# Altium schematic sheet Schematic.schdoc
size 127 x 101 mm
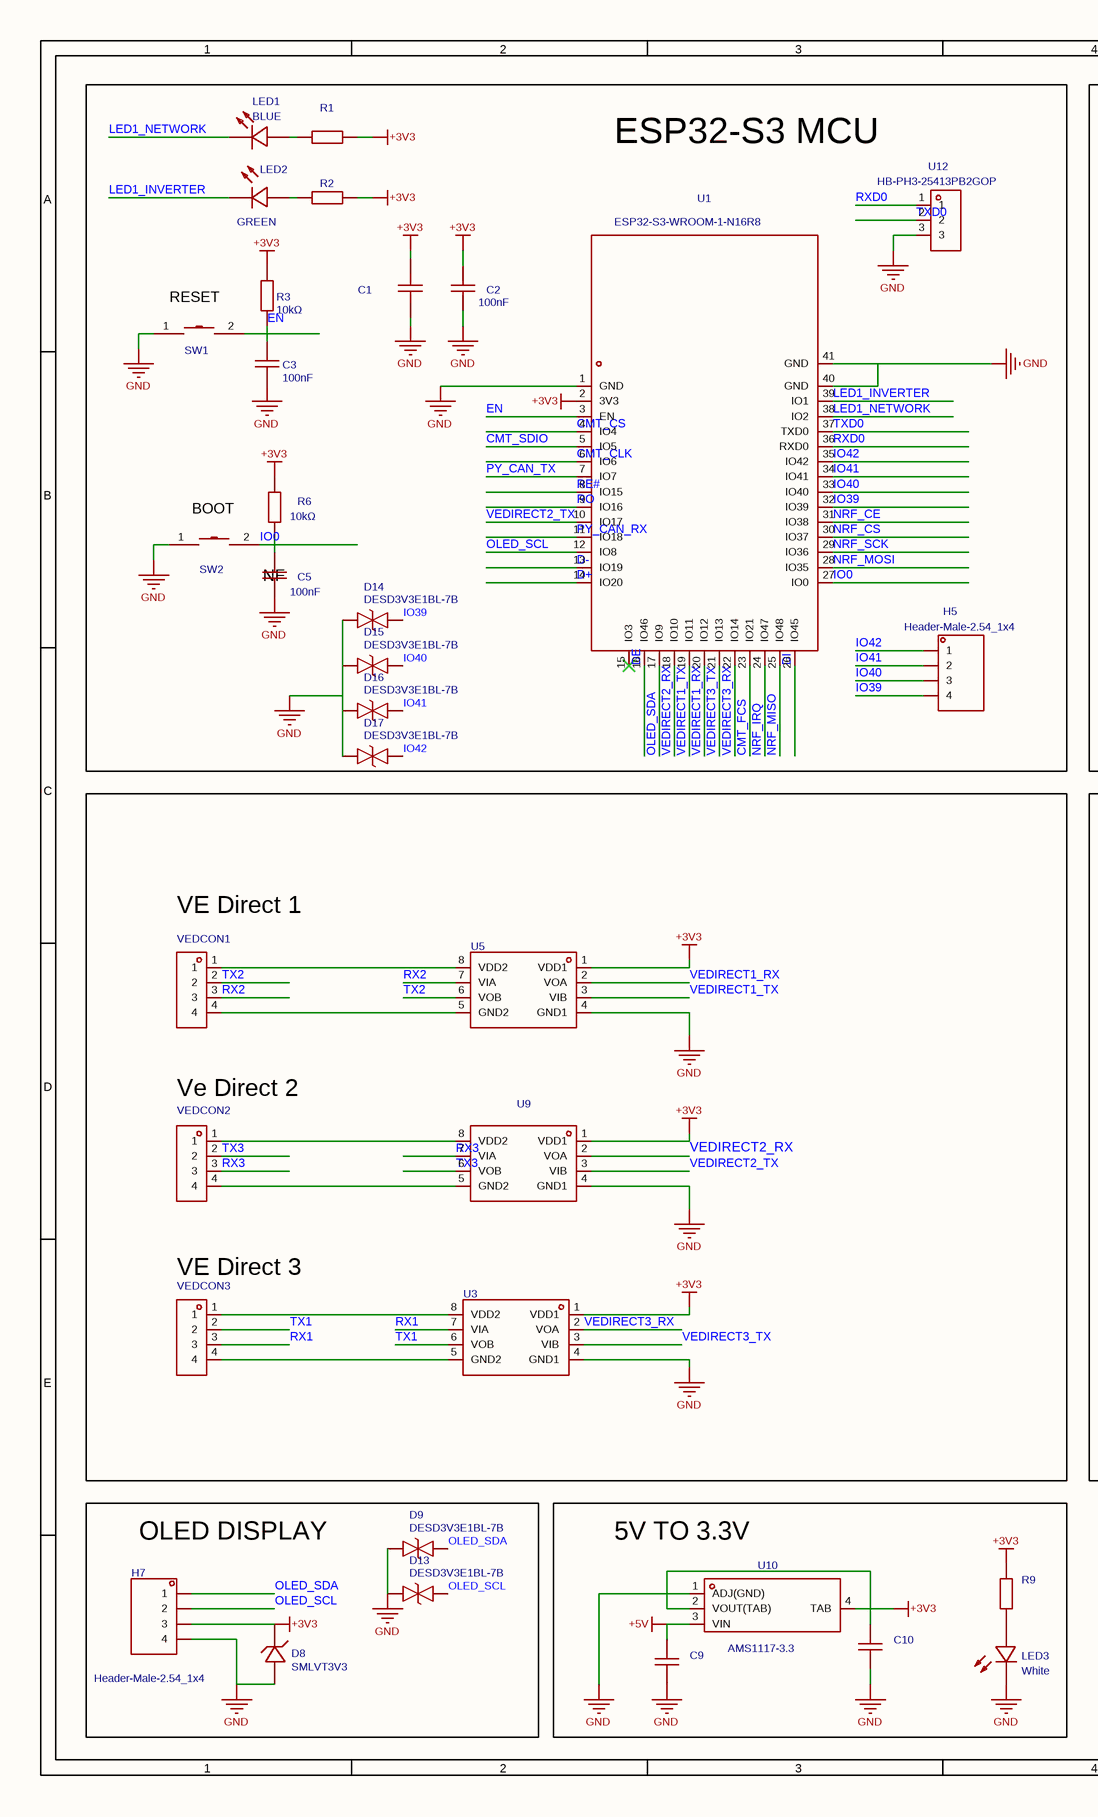
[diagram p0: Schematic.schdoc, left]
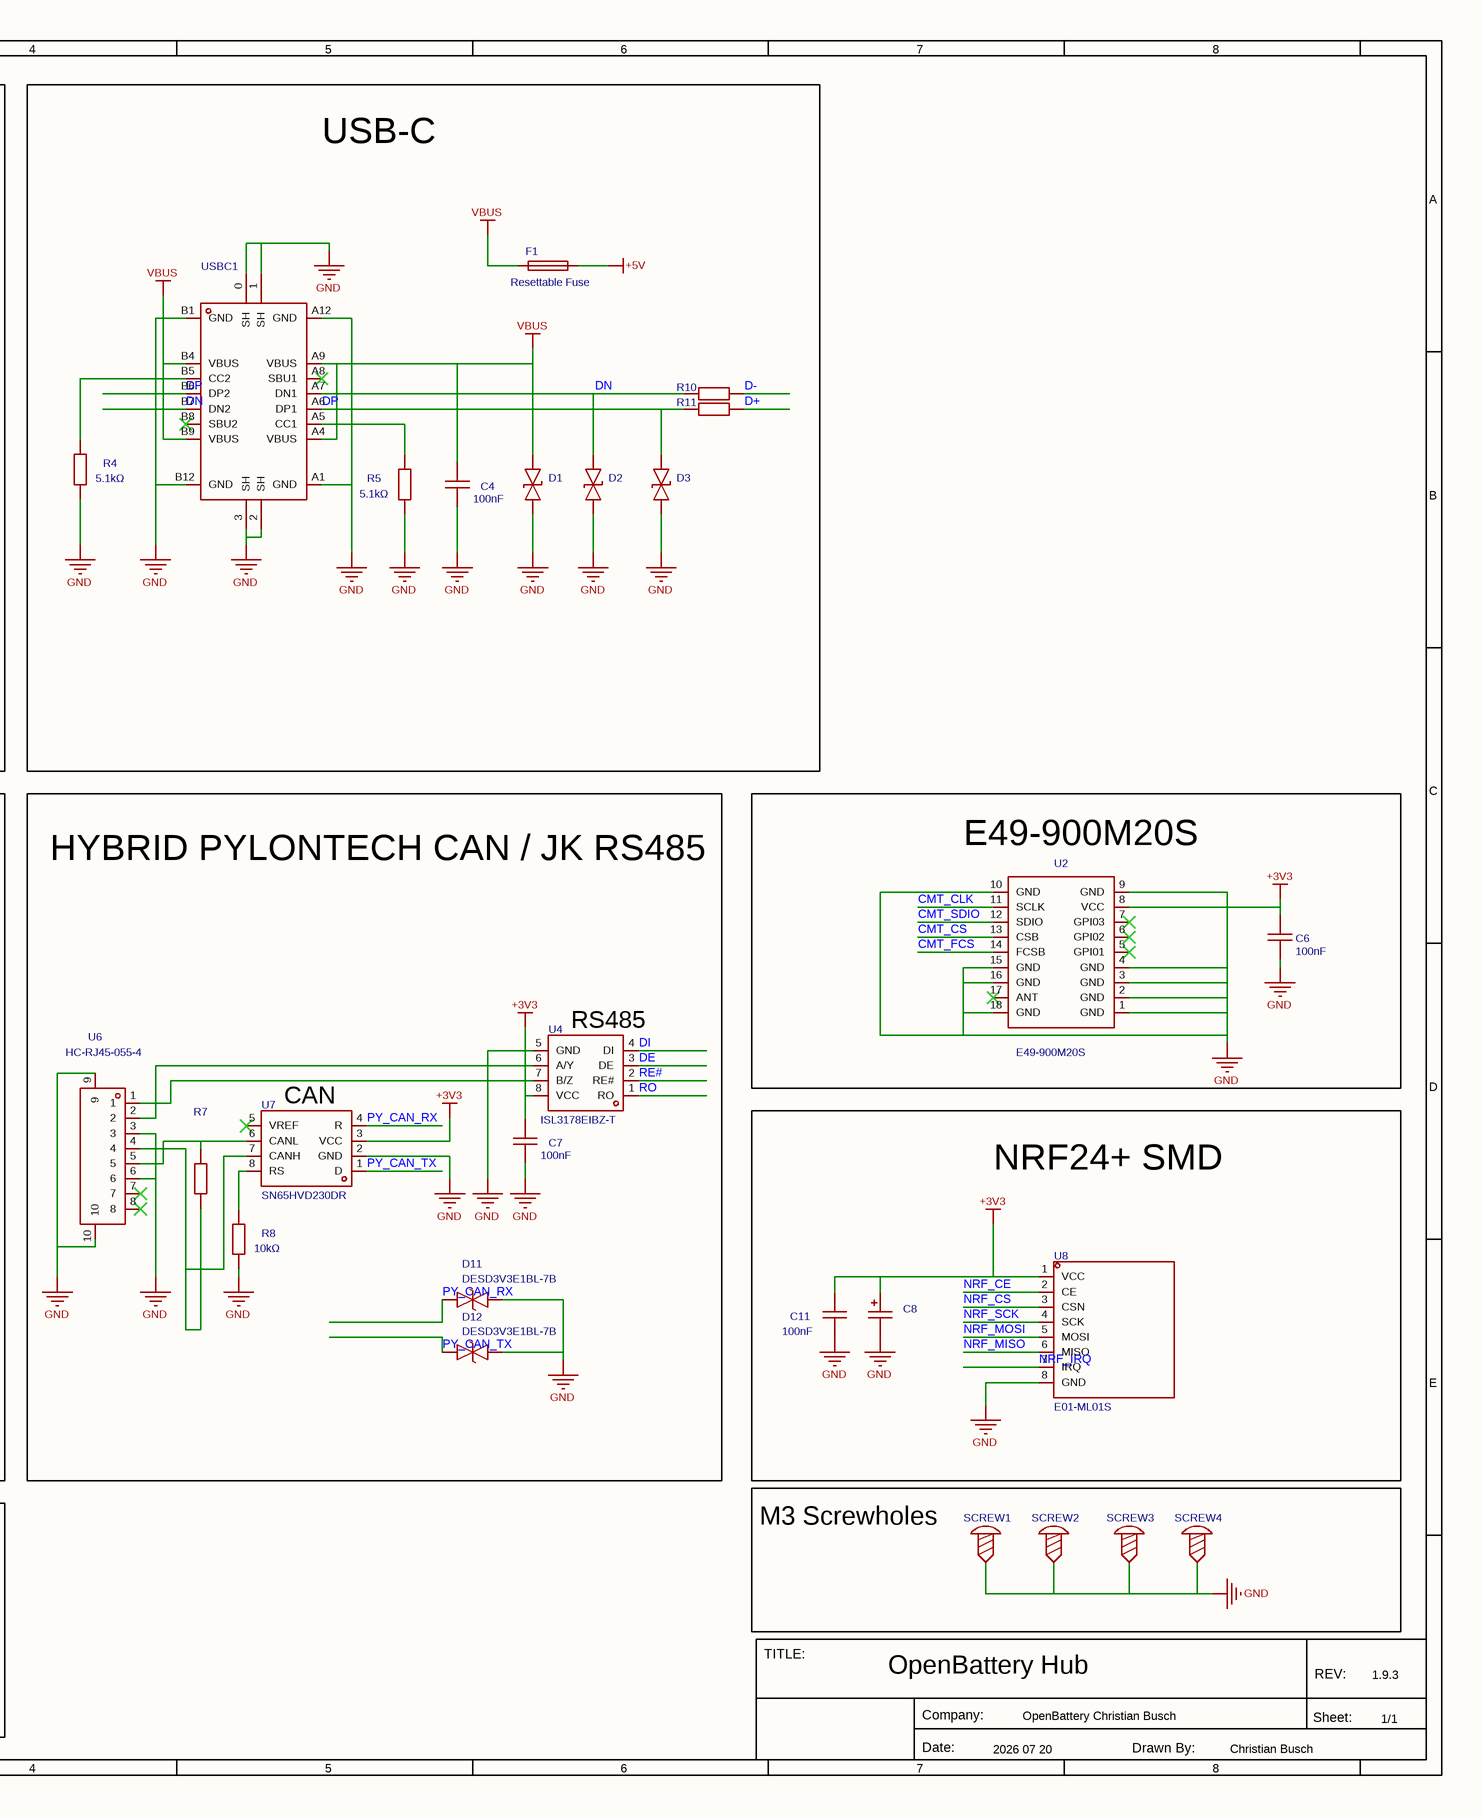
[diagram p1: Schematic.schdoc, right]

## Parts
C1  22uF  [C0402_4]  (value not drawn)
C2  100nF  [C0402_4]
C3  100nF  [C0402_4]
C4  100nF  [C0402_4]
C5  100nF  [C0402_4]
C6  100nF  [C0402_4]
C7  100nF  [C0402_4]
C8  100uF  [CASE-B_3531]  (value not drawn)
C9  10uF  [C0402_4]  (value not drawn)
C10  10uF  [C0402_4]  (value not drawn)
C11  100nF  [C0402_4]
D1  LESD5D5.0CT1G  [SOD-523_L1.2-W0.8-LS1.6-BI_4]  (value not drawn)
D2  LESD5D5.0CT1G  [SOD-523_L1.2-W0.8-LS1.6-BI_4]  (value not drawn)
D3  LESD5D5.0CT1G  [SOD-523_L1.2-W0.8-LS1.6-BI_4]  (value not drawn)
D8  SMLVT3V3  [SMB_L4.6-W3.6-LS5.3-RD_3]
D9  DESD3V3E1BL-7B  [X1-DFN1006-2_L1.0-W0.6-P0.65-BI_2]
D11  DESD3V3E1BL-7B  [X1-DFN1006-2_L1.0-W0.6-P0.65-BI_2]
D12  DESD3V3E1BL-7B  [X1-DFN1006-2_L1.0-W0.6-P0.65-BI_2]
D13  DESD3V3E1BL-7B  [X1-DFN1006-2_L1.0-W0.6-P0.65-BI_2]
D14  DESD3V3E1BL-7B  [X1-DFN1006-2_L1.0-W0.6-P0.65-BI_2]
D15  DESD3V3E1BL-7B  [X1-DFN1006-2_L1.0-W0.6-P0.65-BI_2]
D16  DESD3V3E1BL-7B  [X1-DFN1006-2_L1.0-W0.6-P0.65-BI_2]
D17  DESD3V3E1BL-7B  [X1-DFN1006-2_L1.0-W0.6-P0.65-BI_2]
F1  Resettable Fuse  [F1206_3]
H5  Header-Male-2.54_1x4  [HDR-TH_4P-P2.54-V-M_3]
H7  Header-Male-2.54_1x4  [HDR-TH_4P-P2.54-V-M_3]
LED1  BLUE  [LED0402-R-RD_3]
LED2  GREEN  [LED0402-RD_GREEN_3]
LED3  White  [LED0402-RD_WHITE_3]
R1  1.5kΩ  [R0402_3]  (value not drawn)
R2  1.5kΩ  [R0402_3]  (value not drawn)
R3  10kΩ  [R0402_3]
R4  5.1kΩ  [R0402_3]
R5  5.1kΩ  [R0402_3]
R6  10kΩ  [R0402_3]
R7  120Ω  [R0402_3]  (value not drawn)
R8  10kΩ  [R0402_3]
R9  1.5kΩ  [R0402_3]  (value not drawn)
R10  22Ω  [R0402_3]  (value not drawn)
R11  22Ω  [R0402_3]  (value not drawn)
SCREW1  (no value)  [Screw-Hole-M2]
SCREW2  (no value)  [Screw-Hole-M2]
SCREW3  (no value)  [Screw-Hole-M2]
SCREW4  (no value)  [Screw-Hole-M2]
SW1  TS-1101-C-W  [SW-SMD_L6.0-W3.3-LS8.0_3]  (value not drawn)
SW2  TS-1101-C-W  [SW-SMD_L6.0-W3.3-LS8.0_3]  (value not drawn)
U1  ESP32-S3-WROOM-1-N16R8  [WIRELM-SMD_ESP32-S3-WROOM-1_4]
U2  E49-900M20S  [WIRELM-SMD_E49-400M20S_3]
U3  ADUM1201AR-RL7  [SOIC-8_L4.9-W3.9-P1.27-LS6.0-BL_3]  (value not drawn)
U4  ISL3178EIBZ-T  [SOIC-8_L4.9-W3.9-P1.27-LS6.0-BL_3]
U5  ADUM1201AR-RL7  [SOIC-8_L4.9-W3.9-P1.27-LS6.0-BL_3]  (value not drawn)
U6  HC-RJ45-055-4  [RJ45-SMD_HC-RJ45-055-4_5]
U7  SN65HVD230DR  [SOIC-8_L4.9-W3.9-P1.27-LS6.0-BL_3]
U8  E01-ML01S  [WIRELM-SMD_E01-ML01S_3]
U9  ADUM1201AR-RL7  [SOIC-8_L4.9-W3.9-P1.27-LS6.0-BL_3]  (value not drawn)
U10  AMS1117-3.3  [SOT-223-4_L6.5-W3.5-P2.30-LS7.0-BR_3]
U12  HB-PH3-25413PB2GOP  [HDR-TH_3P-P2.54-V-M_3]
USBC1  TYPE-C-31-M-12  [USB-C_SMD-TYPE-C-31-M-12_3]  (value not drawn)
VEDCON1  PH-4AW_C722777  [CONN-TH_PH-4AW_C722777_3]  (value not drawn)
VEDCON2  PH-4AW_C722777  [CONN-TH_PH-4AW_C722777_3]  (value not drawn)
VEDCON3  PH-4AW_C722777  [CONN-TH_PH-4AW_C722777_3]  (value not drawn)

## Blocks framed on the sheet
E49-900M20S: C6 U2
NRF24+ SMD: C8 C11 U8
M3 Screwholes: SCREW1-SCREW4
OLED DISPLAY: D8 D9 D13 H7
5V TO 3.3V: C9 C10 LED3 R9 U10

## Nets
+3V3: C1.2 C2.2 C6.2 C7.2 C8.1 C10.2 C11.1 D8.1(C) H7.3 R1.1 R2.1 R3.2 R6.2 R9.2 U1.2(3V3) U2.8(VCC) U3.1(VDD1) U4.8(VCC) U5.1(VDD1) U7.3(VCC) U8.1(VCC) U9.1(VDD1) U10.2(VOUT(TAB)) U10.4(TAB)
+5V: C9.1 F1.2 U10.3(VIN)
GND: C1.1 C2.1 C3.1 C4.1 C5.1 C6.1 C7.1 C8.2 C9.2 C10.1 C11.2 D1.1 D2.1 D3.1 D8.2(A) D9.1 D11.2 D12.2 D13.1 D14.1 D15.1 D16.1 D17.1 H7.4 LED3.1(C) R4.1 R5.1 R8.1 SCREW1.1 SCREW2.1 SCREW3.1 SCREW4.1 SW1.1 SW2.1 U1.1(GND) U1.40(GND) U1.41(GND) U2.1(GND) U2.2(GND) U2.3(GND) U2.4(GND) U2.9(GND) U2.10(GND) U2.15(GND) U2.16(GND) U2.18(GND) U3.4(GND1) U4.5(GND) U5.4(GND1) U6.3 U6.6 U6.9 U6.10 U7.2(GND) U8.8(GND) U9.4(GND1) U10.1(ADJ(GND)) U12.3 USBC1.0(SH) USBC1.1(SH) USBC1.2(SH) USBC1.3(SH) USBC1.A1(GND) USBC1.A12(GND) USBC1.B1(GND) USBC1.B12(GND)
VBUS: C4.2 D1.2 F1.1 USBC1.A4(VBUS) USBC1.A9(VBUS) USBC1.B4(VBUS) USBC1.B9(VBUS)
CMT_CLK: U1.6(IO6) U2.11(SCLK)
CMT_CS: U1.4(IO4) U2.13(CSB)
CMT_FCS: U1.23(IO21) U2.14(FCSB)
CMT_SDIO: U1.5(IO5) U2.12(SDIO)
D+: R11.2 U1.14(IO20)
D-: R10.2 U1.13(IO19)
DE: U1.16(IO46) U4.3(DE)
DI: U1.26(IO45) U4.4(DI)
DN: D2.2 R10.1 USBC1.A7(DN1) USBC1.B7(DN2)
DP: D3.2 R11.1 USBC1.A6(DP1) USBC1.B6(DP2)
EN: C3.2 R3.1 SW1.2 U1.3(EN)
IO0: C5.2 R6.1 SW2.2 U1.27(IO0)
IO39: D14.2 H5.4 U1.32(IO39)
IO40: D15.2 H5.3 U1.33(IO40)
IO41: D16.2 H5.2 U1.34(IO41)
IO42: D17.2 H5.1 U1.35(IO42)
LED1_INVERTER: LED2.1(C) U1.39(IO1)
LED1_NETWORK: LED1.2(K) U1.38(IO2)
NRF_CE: U1.31(IO38) U8.2(CE)
NRF_CS: U1.30(IO37) U8.3(CSN)
NRF_IRQ: U1.24(IO47) U8.7(IRQ)
NRF_MISO: U1.25(IO48) U8.6(MISO)
NRF_MOSI: U1.28(IO35) U8.5(MOSI)
NRF_SCK: U1.29(IO36) U8.4(SCK)
OLED_SCL: D13.2 H7.2 U1.12(IO8)
OLED_SDA: D9.2 H7.1 U1.17(IO9)
PY_CAN_RX: D11.1 U1.11(IO18) U7.4(R)
PY_CAN_TX: D12.1 U1.7(IO7) U7.1(D)
RE#: U1.8(IO15) U4.2(RE#)
RO: U1.9(IO16) U4.1(RO)
RX1: U3.7(VIA) VEDCON3.3
RX2: U5.7(VIA) VEDCON1.3
RX3: U9.7(VIA) VEDCON2.3
RXD0: U1.36(RXD0) U12.1
TX1: U3.6(VOB) VEDCON3.2
TX2: U5.6(VOB) VEDCON1.2
TX3: U9.6(VOB) VEDCON2.2
TXD0: U1.37(TXD0) U12.2
VEDIRECT1_RX: U1.20(IO12) U5.2(VOA)
VEDIRECT1_TX: U1.19(IO11) U5.3(VIB)
VEDIRECT2_RX: U1.18(IO10) U9.2(VOA)
VEDIRECT2_TX: U1.10(IO17) U9.3(VIB)
VEDIRECT3_RX: U1.22(IO14) U3.2(VOA)
VEDIRECT3_TX: U1.21(IO13) U3.3(VIB)
NetLED1_1: LED1.1(A) R1.2
NetLED2_2: LED2.2(A) R2.2
NetLED3_2: LED3.2(A) R9.1
NetR4_2: R4.2 USBC1.B5(CC2)
NetR5_2: R5.2 USBC1.A5(CC1)
NetR7_1: R7.1 U6.4 U7.7(CANH)
NetR7_2: R7.2 U6.5 U7.6(CANL)
NetR8_2: R8.2 U7.8(RS)
NetU3_5: U3.5(GND2) VEDCON3.4
NetU3_8: U3.8(VDD2) VEDCON3.1
NetU4_6: U4.6(A/Y) U6.2
NetU4_7: U4.7(B/Z) U6.1
NetU5_5: U5.5(GND2) VEDCON1.4
NetU5_8: U5.8(VDD2) VEDCON1.1
NetU9_5: U9.5(GND2) VEDCON2.4
NetU9_8: U9.8(VDD2) VEDCON2.1

Not connected (* = marked no-connect by the designer): U1 15(IO3)*; U2 5(GPI01)* 6(GPI02)* 7(GPI03)* 17(ANT)*; U6 7* 8*; U7 5(VREF)*; USBC1 A8(SBU1)* B8(SBU2)*

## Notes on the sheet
- 1
- 2
- 3
- 4
- 5
- 6
- 7
- 8
- ESP32-S3 MCU
- USB-C
- A
- (near SW1) RESET
- B
- (near SW2) BOOT
- (near C5) NF
- C
- HYBRID PYLONTECH CAN / JK RS485
- (near VEDCON1) VE Direct 1
- D
- (near VEDCON2) Ve Direct 2
- (near U4) RS485
- (near U7) CAN
- (near VEDCON3) VE Direct 3
- E
- TITLE:
- OpenBattery Hub
- REV:
- 1.9.3
- Date:
- Company:
- 2026 07 20
- OpenBattery Christian Busch
- Drawn By:
- Christian Busch
- Sheet:
- 1/1

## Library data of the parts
C1 = 22uF_1: Manufacturer: muRata(村田); Manufacturer Part: GRM155R60J226ME11D; Origin Footprint: C0402; Add into BOM: yes; Tolerance: ±20%; ModelId: 89fda7647e4f421c9745a20fb37cf343
C2-C7 C11 = 100nF_1: Manufacturer Part: CL05B104KO5NNNC; Manufacturer: SAMSUNG(三星); Convert to PCB: yes; Origin Footprint: C0402; ModelId: 89fda7647e4f421c9745a20fb37cf343
C8 = 100uF_1: Manufacturer: Kyocera AVX; Manufacturer Part: TAJB107K006RNJ; Origin Footprint: CASE-B_3528; Add into BOM: yes; Tolerance: ±10%; Equivalent Series Resistance(ESR): 1.7Ω@100kHz
C9 C10 = 10uF_1: Manufacturer Part: CL05A106MQ5NUNC; Manufacturer: SAMSUNG(三星); Origin Footprint: C0402; Add into BOM: yes; Tolerance: ±20%; ModelId: 89fda7647e4f421c9745a20fb37cf343
D1-D3 = LESD5D5.0CT1G_1: Manufacturer: LRC(乐山无线电); Origin Footprint: SOD-523_L1.2-W0.8-LS1.6-BI; Add into BOM: yes; polarity: Bi-Directional; Reverse Stand-Off Voltage (Vrwm): 5V; Maximum Clamping Voltage: 18.6V; Peak Pulse Current (Ipp)@10/1000us: 9.4A; Breakdown Voltage: 5.6V; Type: ESD; ModelId: 4084e30f0f42442eb5952d3b89d1d381
D8 = SMLVT3V3_1: Manufacturer: ST(意法半导体); Origin Footprint: SMB_L4.6-W3.6-LS5.3-RD; Convert to PCB: yes; ModelId: 6383b9be09eb4825906cf4ce91b85cee
D9 D11-D17 = DESD3V3E1BL-7B: Manufacturer: DIODES(美台); Origin Footprint: X1-DFN1006-2_L1.0-W0.6-P0.65-BI; Convert to PCB: yes; ModelId: ea1bcde2100540c7b34b3a1c7df79444
F1 = Resettable Fuse_1: Manufacturer: JKSEMI(金开盛); Origin Footprint: F1206; Add into BOM: yes
H5 = Header-Male-2.54_1x4_2: Manufacturer: Ckmtw(灿科盟); Manufacturer Part: B-2100S04P-A110; Origin Footprint: HDR-TH_4P-P2.54-V-M; Symbol: Header-Male-2.54_1x4_1; Convert to PCB: yes; ModelId: e591196743ea40f39704c2a63b18db53
H7 = Header-Male-2.54_1x4_1: Manufacturer: Ckmtw(灿科盟); Manufacturer Part: B-2100S04P-A110; Convert to PCB: yes; Origin Footprint: HDR-TH_4P-P2.54-V-M; ModelId: e591196743ea40f39704c2a63b18db53
LED1 = BLUE_1: Manufacturer: EVERLIGHT(亿光); Origin Footprint: LED0402-R-RD; Add into BOM: yes
LED2 = GREEN_1: Manufacturer: TOGIALED(统佳); Origin Footprint: LED0402-RD_GREEN; Add into BOM: yes; Emitted Color: Green-yellow
LED3 = White_1: Manufacturer: TOGIALED(统佳); Manufacturer Part: TJ-S1005SW4TGLCCW-A5; Origin Footprint: LED0402-RD_WHITE; Add into BOM: yes; ModelId: f84adf3c6ce44496ac36796edcfca1f7
R1 R2 = 1.5kΩ_2: Manufacturer: UNI-ROYAL(厚声); Manufacturer Part: 0402WGF1501TCE; Origin Footprint: R0402; Symbol: 1.5kΩ_1; Add into BOM: yes; Tolerance: ±1%; Temperature Coefficient: ±100ppm/℃
R3 R6 R8 = 10kΩ_1: Manufacturer: UNI-ROYAL(厚声); Manufacturer Part: 0402WGF1002TCE; Convert to PCB: yes; Origin Footprint: R0402
R4 R5 = 5.1kΩ_1: Manufacturer: UNI-ROYAL(厚声); Manufacturer Part: 0402WGF5101TCE; Convert to PCB: yes; Origin Footprint: R0402
R7 = 120Ω_1: Manufacturer: UNI-ROYAL(厚声); Manufacturer Part: 0402WGF1200TCE; Origin Footprint: R0402; Add into BOM: yes; Tolerance: ±1%; Temperature Coefficient: ±100ppm/℃
R9 = 1.5kΩ_1: Manufacturer: UNI-ROYAL(厚声); Manufacturer Part: 0402WGF1501TCE; Origin Footprint: R0402; Add into BOM: yes; Tolerance: ±1%; Temperature Coefficient: ±100ppm/℃
R10 = 22Ω_1: Manufacturer: UNI-ROYAL(厚声); Manufacturer Part: 0402WGF220JTCE; Origin Footprint: R0402; Add into BOM: yes; Tolerance: ±1%; Temperature Coefficient: ±100ppm/℃
R11 = 22Ω_2: Manufacturer: UNI-ROYAL(厚声); Manufacturer Part: 0402WGF220JTCE; Origin Footprint: R0402; Symbol: 22Ω_1; Add into BOM: yes; Tolerance: ±1%; Temperature Coefficient: ±100ppm/℃
SCREW1-SCREW4 = screw-hole-m3: AddInBom: yes
SW1 SW2 = TS-1101-C-W_1: Manufacturer: XKB Connectivity(中国星坤); 3DModel: SW-SMD_L6.0-W3.3-H5-LS8.0; Convert to PCB: yes; Origin Footprint: SW-SMD_L6.0-W3.3-LS8.0
U1 = ESP32-S3-WROOM-1-N16R8_1: Manufacturer: ESPRESSIF(乐鑫); Origin Footprint: WIRELM-SMD_ESP32-S3-WROOM-1; Add into BOM: yes; ModelId: dbf21c799c1c42a38df84fd714a1a1c8
U2 = E49-900M20S_1: Manufacturer: EBYTE(亿佰特); Convert to PCB: yes; Origin Footprint: WIRELM-SMD_E49-400M20S; ModelId: c53069f879104396b7c6ba6404deb9e6
U3 U5 U9 = ADUM1201AR-RL7_1: Manufacturer: Analog Devices; Convert to PCB: yes; Origin Footprint: SOIC-8_L4.9-W3.9-P1.27-LS6.0-BL
U4 = ISL3178EIBZ-T_1: Manufacturer: RENESAS(瑞萨)/IDT; Origin Footprint: SOIC-8_L4.9-W3.9-P1.27-LS6.0-BL; Add into BOM: yes; Types: transceiver; Driver/receiver: 1/1; Data Rate: 20Mbps; Supply Voltage: 3V3.6V
U6 = HC-RJ45-055-4_1: Manufacturer: HCTL(华灿天禄); Origin Footprint: RJ45-SMD_HC-RJ45-055-4_2; Add into BOM: yes; Connector Type: RJReceptacle; USOC Codes: RJ45; Number of Ports: 1; Shielding: 有屏蔽; LED: 不带LED
U7 = SN65HVD230DR_1: Manufacturer: TI(德州仪器); Origin Footprint: SOIC-8_L4.9-W3.9-P1.27-LS6.0-BL; Add into BOM: yes; Data Rate: 1Mbps; Supply Voltage: 3V3.6V
U8 = E01-ML01S_1: Manufacturer: EBYTE(亿佰特); Origin Footprint: WIRELM-SMD_E01-ML01S; Add into BOM: yes
U10 = AMS1117-3.3_1: Manufacturer: UMW(友台半导体); Origin Footprint: SOT-223-4_L6.5-W3.5-P2.30-LS7.0-BR; Add into BOM: yes; Maximum Input Voltage: 12V; Output Voltage: 3.3V; MAX Output Current: 1A; Power Supply Rejection Ratio (PSRR): 60dB@(120Hz); Dropout Voltage: 1.3V@(1A); Output Polarity: Positive electrode; Number of Outputs: 1
U12 = HB-PH3-25413PB2GOP_1: Manufacturer: HANBO(汉博); Origin Footprint: HDR-TH_3P-P2.54-V-M; Convert to PCB: yes
USBC1 = TYPE-C-31-M-12_1: Manufacturer: 韩国韩荣; Origin Footprint: USB-C_SMD-TYPE-C-31-M-12; Add into BOM: yes; Connector Type: Type-C; Gender: Female; Number of Ports: 1; Number of Contacts: 16P; Current Rating - Power (Max): 5A; ModelId: d4850b6bcfb24c8f8ccb21298ff9a0df
VEDCON1-VEDCON3 = PH-4AW_C722777_1: Manufacturer: CAX; Manufacturer Part: PH-4AW; Convert to PCB: yes; Origin Footprint: CONN-TH_PH-4AW_C722777; ModelId: 68110d72d276454db66ea60548f8e564libraries; ModelTransform: 1181.1,1181.1,1181.1,0,180,0,0,0,0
